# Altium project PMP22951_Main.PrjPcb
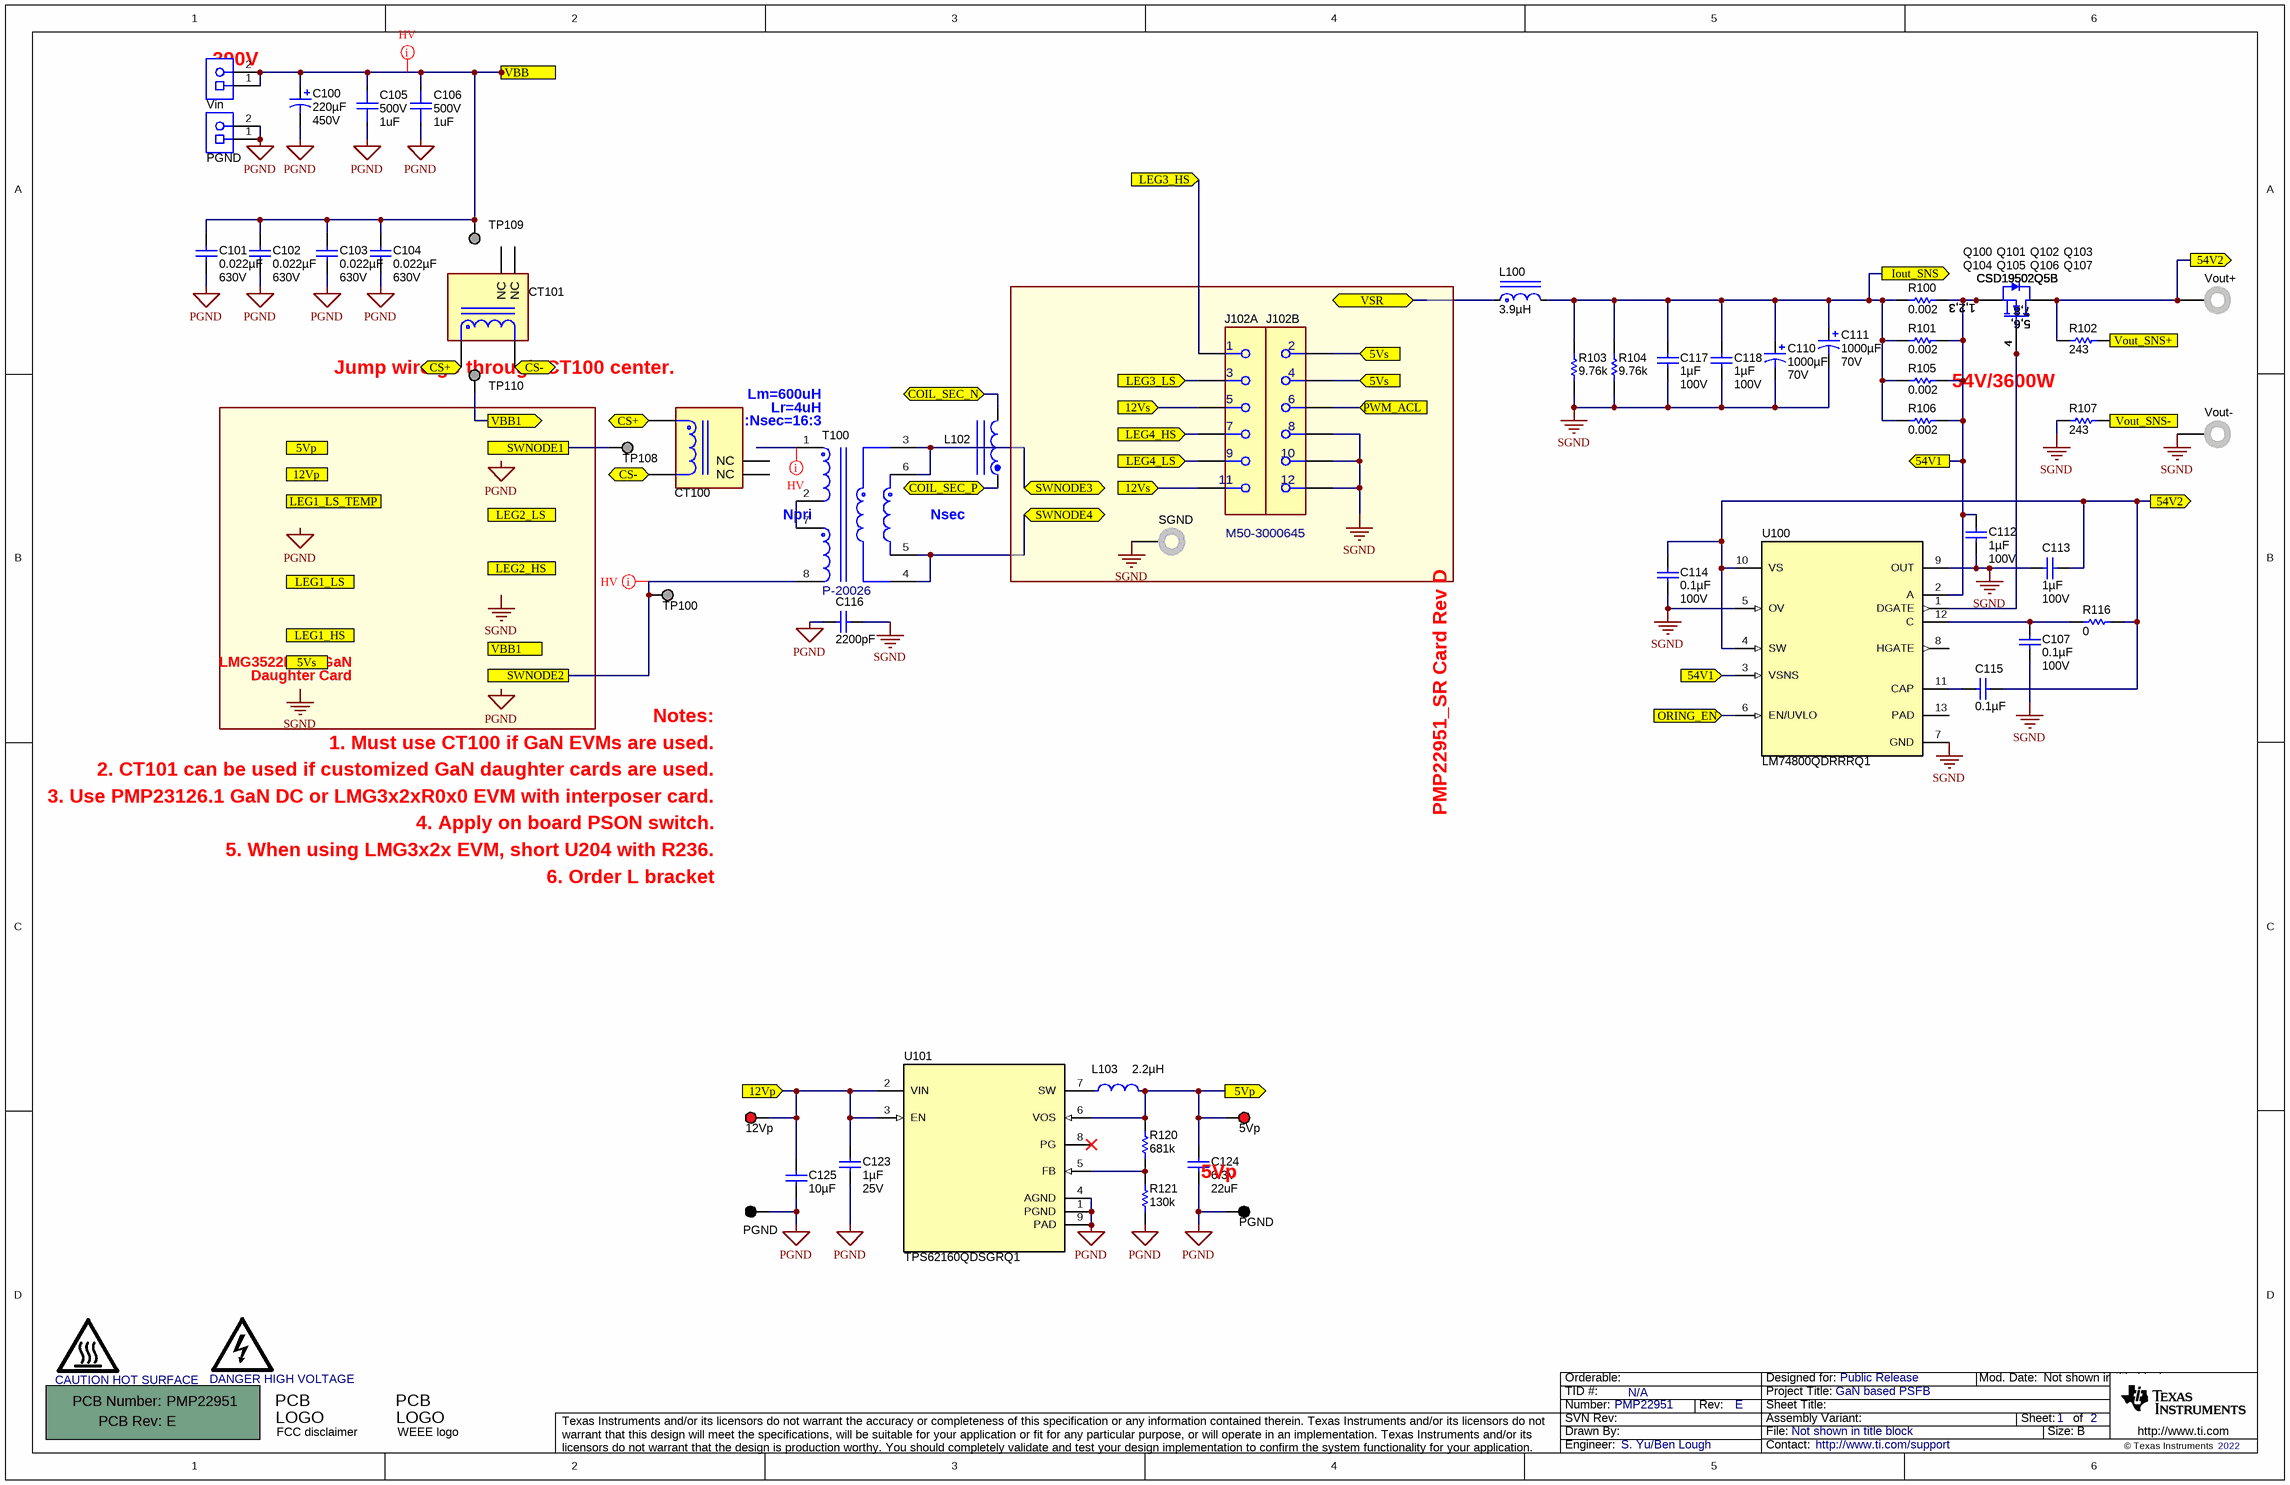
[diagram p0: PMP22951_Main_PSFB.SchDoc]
CopyrightYear: 2022; PCB_Layout: S. Yu/Ben Lough; PCB_Rev: E; PRJ_Customer: Public Release; PRJ_Engineer: S. Yu/Ben Lough; PRJ_Number: PMP22951; PRJ_Title: GaN based PSFB; SCH_Rev: E; TechSupport: http://www.ti.com/support; TID: N/A
2 sheets, 142 parts. Net scope: flat (ports and power ports of the same name join across sheets).
Board file: PMP22951_Main_PCB.PcbDoc
Sheets:
  PMP22951_Main_PSFB.SchDoc
  PMP22951_Main_Controller.SchDoc

## Sheet PMP22951_Main_PSFB.SchDoc
size 431 x 279 mm; Date: Not shown in title block; ApprovedBy: Not shown in title block; CheckedBy: Not shown in title block; Author: Not shown in title block; CompanyName: Not shown in title block; Engineer: Not shown in title block; Organization: Not shown in title block; Address1: Not shown in title block; Address2: Not shown in title block; Address3: Not shown in title block; Address4: Not shown in title block; DocumentNumber: 1; Revision: Use project parameter SCH_Rev; SheetNumber: 1; SheetTotal: 2; PageSetup: Record=PageOptions¦CenterHorizontal=True¦CenterVertical=True¦PrintScale=1.00¦XCorrection=1.00¦YCorrection=1.00¦PrintKind=0¦BorderSize=5000000¦LeftOffset=0¦BottomOffset=0¦Orientation=2¦PaperLength=1000¦PaperWidth=1000¦Scale=100¦PaperSource=15¦PrintQuality=600¦MediaType=1¦DitherType=10¦PaperKind=Letter¦PrintScaleMode=1

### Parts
(Parts that share a designator on the sheet are numbered #1, #2 ... from top to bottom, then left to right.)
5Vp  5000  [Keystone5000]  (value not drawn)
12Vp  5000  [Keystone5000]  (value not drawn)
!PCB100  Printed Circuit Board  (value not drawn)  (mechanical)
C100  ValueDisplayed: 220µF  Value2: 450V  [HXG_2500x4000]  (hidden comment: 450HXG220MEFCSN25X40)
C101  ValueDisplayed: 0.022µF  Value2: 630V  [1206]  (hidden comment: CL31B223KHHNNNE)
C102  ValueDisplayed: 0.022µF  Value2: 630V  [1206]  (hidden comment: CL31B223KHHNNNE)
C103  ValueDisplayed: 0.022µF  Value2: 630V  [1206]  (hidden comment: CL31B223KHHNNNE)
C104  ValueDisplayed: 0.022µF  Value2: 630V  [1206]  (hidden comment: CL31B223KHHNNNE)
C105  VDC_V: 500V  ValueDisplayed: 1uF  [FP-B58031U5105M062_SMD2-MFG]  (hidden comment: B58031U5105M062)
C106  VDC_V: 500V  ValueDisplayed: 1uF  [FP-B58031U5105M062_SMD2-MFG]  (hidden comment: B58031U5105M062)
C107  ValueDisplayed: 0.1µF  Value2: 100V  [0805_HV]  (hidden comment: C0805C104K1RACTU)
C110  ValueDisplayed: 1000µF  Value2: 70V  [HE_1800x2500]  (hidden comment: 70RXA1000M18X25)
C111  ValueDisplayed: 1000µF  Value2: 70V  [HE_1800x2500]  (hidden comment: 70RXA1000M18X25)
C112  ValueDisplayed: 1µF  Value2: 100V  [1206_180]  (hidden comment: GCM31CR72A105KA03)
C113  ValueDisplayed: 1µF  Value2: 100V  [1206_180]  (hidden comment: GCM31CR72A105KA03)
C114  ValueDisplayed: 0.1µF  Value2: 100V  [0805_HV]  (hidden comment: C0805C104K1RACTU)
C115  ValueDisplayed: 0.1µF  [0603]  (hidden comment: 06033C104JAT2A)
C116  ValueDisplayed: 2200pF  [E_900x700x900]  (hidden comment: DE6E3KJ222MN3A)
C117  ValueDisplayed: 1µF  Value2: 100V  [1206_180]  (hidden comment: GCM31CR72A105KA03)
C118  ValueDisplayed: 1µF  Value2: 100V  [1206_180]  (hidden comment: GCM31CR72A105KA03)
C123  Cap_F: 1µF  VDC_V: 25V  [0805_HV]  (hidden comment: C0805C105K3RACTU)
C124  VDC_V: 6.3V  ValueDisplayed: 22uF  [0805_HV]  (hidden comment: CL21A226KQQNNNE)
C125  ValueDisplayed: 10µF  [1206_180]  (hidden comment: GCM31CR71C106KA64L)
CT100  PAS6282NL  [FP-PAS6282NL_PTH_12MM5_4MM5-MFG]  (value not drawn)
CT101  PAS6282NL  [FP-PAS6282NL_PTH_12MM5_4MM5-MFG]  (value not drawn)
J102  M50-3000645  [FP-M50-3000645_HDR12-MFG]  (parts A,B of 2)
L100  value 3.9µH  [FP-PAL6567.421NL_PTH_IND_34MM0_9MM5-MFG]  (hidden comment: PAL6431.392NL)
L102  RLTI-1310  [RLTI-1310]  (value not drawn)
L103  Ind_H: 2.2µH  [FP-74438336010_SMD2-MFG]  (hidden comment: 74438336022)
LOGO100  CAUTION HOT SURFACE  [IEC_HotSurface_Small]  (no BOM)
LOGO101  DANGER HIGH VOLTAGE  [IEC_HighVoltage_Small]  (no BOM)
Logo102  FCC disclaimer  [FCC_disclaimer]  (no BOM)
Logo103  WEEE logo  [WEEE_Minimum]  (no BOM)
PGND#1  1715721  [PhoenixContact_1715721]  (value not drawn)
PGND#2  5001  [Keystone5001]  (value not drawn)
PGND#3  5001  [Keystone5001]  (value not drawn)
Q100  CSD19502Q5B  [DNK0008A]
Q101  CSD19502Q5B  [DNK0008A]
Q102  CSD19502Q5B  [DNK0008A]
Q103  CSD19502Q5B  [DNK0008A]
Q104  CSD19502Q5B  [DNK0008A]
Q105  CSD19502Q5B  [DNK0008A]
Q106  CSD19502Q5B  [DNK0008A]
Q107  CSD19502Q5B  [DNK0008A]
R100  ValueDisplayed: 0.002  [2010]  (hidden comment: PMR50HZPFV2L00)
R101  ValueDisplayed: 0.002  [2010]  (hidden comment: PMR50HZPFV2L00)
R102  ValueDisplayed: 243  [0603]  (hidden comment: CRCW0603243RFKEA)
R103  ValueDisplayed: 9.76k  [1206]  (hidden comment: RC1206FR-079K76L)
R104  ValueDisplayed: 9.76k  [1206]  (hidden comment: RC1206FR-079K76L)
R105  ValueDisplayed: 0.002  [2010]  (hidden comment: PMR50HZPFV2L00)
R106  ValueDisplayed: 0.002  [2010]  (hidden comment: PMR50HZPFV2L00)
R107  ValueDisplayed: 243  [0603]  (hidden comment: CRCW0603243RFKEA)
R116  ValueDisplayed: 0  [0603]  (hidden comment: CRCW06030000Z0EA)
R120  ValueDisplayed: 681k  [0402]  (hidden comment: CRCW0402681KFKED)
R121  ValueDisplayed: 130k  [0402]  (hidden comment: CRCW0402130KFKED)
SGND#1  575-4  [Keystone_575-4]  (value not drawn)
T100  P-20026  [FP-P-20026_SMT8_38MM0_24MM40-MFG]
TP100  Suggest using a net name here  [Mill-Max_0312-0-15-15-34-27-10-0]  (value not drawn)
TP108  Suggest using a net name here  [Mill-Max_0312-0-15-15-34-27-10-0]  (value not drawn)
TP109  Suggest using a net name here  [Mill-Max_0312-0-15-15-34-27-10-0]  (value not drawn)
TP110  Suggest using a net name here  [Mill-Max_0312-0-15-15-34-27-10-0]  (value not drawn)
U100  LM74800QDRRRQ1  [DRR0012E]
U101  TPS62160QDSGRQ1  [DSG0008A]
Vin  1715721  [PhoenixContact_1715721]  (value not drawn)
Vout+  575-4  [Keystone_575-4]  (value not drawn)
Vout-  575-4  [Keystone_575-4]  (value not drawn)

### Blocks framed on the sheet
PMP22951_SR Card Rev D: J102 SGND#1

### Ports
5Vp (in), 5Vp (out), 5Vs (in), 12Vp (in), 12Vs (in), 54V1 (in), 54V1 (out), 54V2 (out), COIL_SEC_N (bidir), COIL_SEC_P (bidir), CS+ (bidir), CS- (bidir), Iout_SNS (out), LEG1_HS (in), LEG1_LS (in), LEG1_LS_TEMP (in), LEG2_HS (in), LEG2_LS (in), LEG3_HS (in), LEG3_LS (in), LEG4_HS (in), LEG4_LS (in), ORING_EN (in), PWM_ACL (in), SWNODE1, SWNODE2, SWNODE3 (bidir), SWNODE4 (bidir), VBB1 (in), VBB1 (out), VBB (out), Vout_SNS+ (out), Vout_SNS- (out), VSR (bidir)

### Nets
PGND: C100.2(-) C101.2 C102.2 C103.2 C104.2 C105.1 C106.1 C116.1 C123.2 C124.2 C125.2 PGND#1.1 PGND#1.2 PGND#2.1 PGND#3.1 R121.1 U101.1(PGND) U101.4(AGND) U101.9(PAD)
SGND: C107.2 C110.2(-) C111.2(-) C112.1 C113.2 C114.2 C116.2 C117.2 C118.2 J102.8 J102.10 J102.12 R103.1 R104.1 R107.1 SGND#1.1 U100.5(OV) U100.7(GND) U100.9(OUT) Vout-.1
5Vp: 5Vp.1 C124.1 L103.2 R120.2 U101.6(VOS) ; port 5Vp
5Vs: J102.2 J102.4 ; port 5Vs
12Vp: 12Vp.1 C123.1 C125.1 U101.2(VIN) U101.3(EN) ; port 12Vp
12Vs: J102.5 J102.11 ; port 12Vs
54V1: C112.2 Q100.1(S) Q100.2(S) Q100.3(S) Q101.1(S) Q101.2(S) Q101.3(S) Q102.1(S) Q102.2(S) Q102.3(S) Q103.1(S) Q103.2(S) Q103.3(S) Q104.1(S) Q104.2(S) Q104.3(S) Q105.1(S) Q105.2(S) Q105.3(S) Q106.1(S) Q106.2(S) Q106.3(S) Q107.1(S) Q107.2(S) Q107.3(S) R100.2 R101.2 R105.2 R106.2 U100.2(A) U100.3(VSNS) ; port 54V1
54V2: C113.1 C114.1 C115.1 Q100.5(D) Q100.6(D) Q100.7(D) Q100.8(D) Q100.9(D) Q101.5(D) Q101.6(D) Q101.7(D) Q101.8(D) Q101.9(D) Q102.5(D) Q102.6(D) Q102.7(D) Q102.8(D) Q102.9(D) Q103.5(D) Q103.6(D) Q103.7(D) Q103.8(D) Q103.9(D) Q104.5(D) Q104.6(D) Q104.7(D) Q104.8(D) Q104.9(D) Q105.5(D) Q105.6(D) Q105.7(D) Q105.8(D) Q105.9(D) Q106.5(D) Q106.6(D) Q106.7(D) Q106.8(D) Q106.9(D) Q107.5(D) Q107.6(D) Q107.7(D) Q107.8(D) Q107.9(D) R102.1 R116.2 U100.4(SW) U100.10(VS) Vout+.1 ; port 54V2
COIL_SEC_N: L102.2 ; port COIL_SEC_N
COIL_SEC_P: L102.1 ; port COIL_SEC_P
CS+: CT100.1 CT101.1 ; port CS+
CS-: CT100.3 CT101.3 ; port CS-
Iout_SNS: C110.1(+) C111.1(+) C117.1 C118.1 L100.2(F) R100.1 R101.1 R103.2 R104.2 R105.1 R106.1 ; port Iout_SNS
LEG3_HS: J102.1 ; port LEG3_HS
LEG3_LS: J102.3 ; port LEG3_LS
LEG4_HS: J102.7 ; port LEG4_HS
LEG4_LS: J102.9 ; port LEG4_LS
ORING_EN: U100.6(EN/UVLO) ; port ORING_EN
PWM_ACL: J102.6 ; port PWM_ACL
SWNODE1: TP108.1 ; port SWNODE1
SWNODE2: T100.8 TP100.1 ; port SWNODE2
SWNODE3: T100.3 T100.6 ; port SWNODE3
SWNODE4: T100.4 T100.5 ; port SWNODE4
VBB: C100.1(+) C101.1 C102.1 C103.1 C104.1 C105.2 C106.2 TP109.1 Vin.1 Vin.2 ; port VBB
VBB1: TP110.1 ; port VBB1
Vout_SNS+: R102.2 ; port Vout_SNS+
Vout_SNS-: R107.2 ; port Vout_SNS-
VSR: L100.1(S) ; port VSR
NetC107_1: C107.1 R116.1 U100.12(C)
NetC115_2: C115.2 U100.11(CAP)
NetL103_1: L103.1 U101.7(SW)
NetQ100_4: Q100.4(G) Q101.4(G) Q102.4(G) Q103.4(G) Q104.4(G) Q105.4(G) Q106.4(G) Q107.4(G) U100.1(DGATE)
NetR120_1: R120.1 R121.2 U101.5(FB)
NetT100_2: T100.2 T100.7

Not connected (* = marked no-connect by the designer): CT100 2(NC) 4(NC); CT101 2(NC) 4(NC); T100 1; U100 8(HGATE) 13(PAD); U101 8(PG)*

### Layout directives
net class HV: NetT100_1, SWNODE2, VBB

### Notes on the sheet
- 390V
- Jump wire go through CT100 center.
- (near T100) Npri:Nsec=16:3
- (near T100) Lm=600uH
- (near T100) Lr=4uH
- 54V/3600W
- Npri
- (near T100) Nsec
- Daughter Card
- LMG3522R030 GaN
- Notes:
- 1. Must use CT100 if GaN EVMs are used.
- 2. CT101 can be used if customized GaN daughter cards are used.
- 3. Use PMP23126.1 GaN DC or LMG3x2xR0x0 EVM with interposer card.
- 4. Apply on board PSON switch.
- 6. Order L bracket
- 5. When using LMG3x2x EVM, short U204 with R236.
- 5Vp
- Labels drawn without touching a wire or pin: PGND, SGND

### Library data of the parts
5Vp 12Vp = 5000: Test Point, Miniature, Red, TH; Manufacturer: Keystone; CompType: Test Point Loop; ContactFinish: Silver; Green_Lifecycle: Active; Green_REACh: Passed
!PCB100 = CMP-0003618-2: Manufacturer: Any; PartNumber: PMP22951
C100 = 450HXG220MEFCSN25X40: CAP, AL, 220 µF, 450 V, +/- 20%, TH; Manufacturer: Rubycon; Polarized: Y; CompType: Capacitor; Value: 220uF; U/M: EA; Cap_F: 0.00022; Tolerance_%: 20; VDC_V: 450; IRMS_A: 1.97; TaMin_C: -25; TaMax_C: 105; Cap_Case: 25x40mm; SizeAreaWB_mm2: 729; SizeArea_mm2: 625; SizeX_mm: 25; SizeZ_mm: 42; AEC Category: Q200; AEC Qualified: N
C101-C104 = VJ1206Y223KXGAT5Z: CAP, CERM, 0.022 µF, 630 V,+/- 10%, X7R, 1206; Manufacturer: Samsung Electro-Mechanics; Polarized: N; CompType: Capacitor; Value: 0.022uF; U/M: EA; Cap_F: 0.000000022; Tolerance_%: 10; VDC_V: 630; TaMin_C: -55; TaMax_C: 125; SizeArea_mm2: 5.12; SizeAreaWB_mm2: 10.92; SizeX_mm: 3.2; SizeY_mm: 1.6; SizeZ_mm: 1.35; AEC Category: Q200
C105 C106 = CMP-0091050-1: TDK 1µF Multilayer Ceramic Capacitor MLCC 500V dc ±20% SMD; AEC Grade: Grade 0; AEC Qualified: Yes; SizeZ_mm: 4.5mm
C107 C114 = C0805C104K1RACTU: CAP, CERM, 0.1 µF, 100 V,+/- 10%, X7R, 0805; Manufacturer: Kemet; Polarized: N; CompType: Capacitor; Value: 0.1uF; U/M: EA; Cap_F: 0.0000001; Tolerance_%: 10; ESR_ohm: 0.064; Value1: 0.064 ohm; VDC_V: 100; IRMS_A: 1.64; TaMin_C: -55; TaMax_C: 125; Cap_Case: 0805; SizeArea_mm2: 2.5; SizeAreaWB_mm2: 6.75; SizeX_mm: 2; SizeY_mm: 1.25; SizeZ_mm: 1.45; AEC Category: Q200; Green_Lifecycle: Active; Green_REACh: Passed
C110 C111 = UHE1H122MHD6: CAP, AL, 1000 µF, 70 V, +/- 20%, TH; Manufacturer: Rubycon; Polarized: Y; CompType: Capacitor; Value: 1000uF; U/M: EA; Cap_F: 0.0012; Tolerance_%: 20; IRMS_A: 2.74; TaMin_C: -40; TaMax_C: 105; Cap_Case: 18x25mm; SizeAreaWB_mm2: 400; SizeArea_mm2: 324; SizeX_mm: 18; SizeZ_mm: 27; AEC Category: Q200; AEC Qualified: N
C112 C113 C117 C118 = GCM31CR72A105KA03: CAP, CERM, 1 µF, 100 V,+/- 10%, X7R, AEC-Q200 Grade 1, 1206; Manufacturer: MuRata; Polarized: N; CompType: Capacitor; Value: 1uF; U/M: EA; Cap_F: 0.000001; Tolerance_%: 10; VDC_V: 100; TaMin_C: -55; TaMax_C: 125; Cap_Case: 1206; SizeArea_mm2: 5.12; SizeAreaWB_mm2: 10.92; SizeX_mm: 3.2; SizeY_mm: 1.6; SizeZ_mm: 1.8; AEC Category: Q200; AEC Qualified: Y; AEC Grade: 1
C115 = 06033C104JAT2A: CAP, CERM, 0.1 µF, 25 V,+/- 5%, X7R, 0603; Manufacturer: AVX; Polarized: N; CompType: Capacitor; Value: 0.1uF; U/M: EA; Cap_F: 0.0000001; Tolerance_%: 5; ESR_ohm: 0.05; Value1: 0.05 ohm; VDC_V: 25; Value2: 25V; TaMin_C: -55; TaMax_C: 125; SizeArea_mm2: 1.28; SizeAreaWB_mm2: 4.68; SizeX_mm: 1.6; SizeY_mm: 0.8; SizeZ_mm: 1; AEC Category: Q200; Green_Lifecycle: Active; Green_REACh: Passed
C116 = DE6E3KJ222MN3A: CAP, CERM, 2200 pF, 300 V, +/- 20%, E, TH, 2- Leads, Body 9x7mm, Pin Spacing 7.5mm; Manufacturer: MuRata; Polarized: N; CompType: Capacitor; Value: 2200pF; U/M: EA; Cap_F: 0.0000000022; Tolerance_%: 20; Value1: Unknown; VDC_V: 300; Value2: 300V; TaMin_C: -40; TaMax_C: 125; Cap_Case: 9x7x9mm; SizeArea_mm2: 63; SizeAreaWB_mm2: 99; SizeX_mm: 9; SizeY_mm: 7; SizeZ_mm: 12; AEC Category: Q200
C123 = CMP-0007728-2: CAP, CERM, 1 uF, 25 V, +/- 10%, X7R, 0805; Manufacturer: Kemet; TaMin_C: -55°C; Polarized: N; SizeAreaWB_mm2: 6.75; Value1: Unknown; U/M: EA; Value: 1uF; TaMax_C: 125°C; SizeZ_mm: 1.45; SizeX_mm: 2; SizeY_mm: 1.25; Cap_Case: 0805; SizeArea_mm2: 2.5; CompType: Capacitor; AEC Category: Q200
C124 = CMP-0007989-2: CAP, CERM, 22 uF, 6.3 V, +/- 10%, X5R, 0805; Manufacturer: Samsung Electro-Mechanics; TaMin_C: -55°C; Polarized: N; SizeAreaWB_mm2: 6.75; Value1: Unknown; U/M: EA; Value: 22uF; TaMax_C: 85°C; SizeZ_mm: 1.45; SizeX_mm: 2; SizeY_mm: 1.25; Cap_Case: 0805; SizeArea_mm2: 2.5; CompType: Capacitor; Cap_F: 22µF; AEC Category: Q200
C125 = GCM31CR71C106KA64L: CAP, CERM, 10 µF, 16 V,+/- 10%, X7R, AEC-Q200 Grade 1, 1206; Manufacturer: MuRata; Polarized: N; CompType: Capacitor; Value: 10uF; U/M: EA; Cap_F: 0.00001; Tolerance_%: 10; VDC_V: 16; Value2: 16V; TaMin_C: -55; TaMax_C: 125; Cap_Case: 1206; SizeArea_mm2: 5.12; SizeAreaWB_mm2: 10.92; SizeX_mm: 3.2; SizeY_mm: 1.6; SizeZ_mm: 1.8; AEC Category: Q200; AEC Qualified: Y; AEC Grade: 1; Green_Lifecycle: Active; Green_REACh: Passed
CT100 CT101 = CMP-0091119-1: Inductor PTH 3.3mH 300mOhm; Manufacturer: Pulse Electronics; SizeZ_mm: 13.5mm; AEC Qualified: No; DCR_ohm: 3d; Test Frequency: 100kHz
J102 = CMP-0094055-1: 12 Position Receptacle Connector 0.050" (1.27mm) Through Hole Gold; Manufacturer: Harwin; AEC Qualified: No; Is Female: yes; ContactFinish: Gold,Nickel; SizeZ_mm: 4.55mm; Current_A: 1A; Conn Gender: Female; Conn Orientation: Vertical; Row_Count: 2
L100 = CMP-0093530-1: INDUCTOR, POWER, EP33, TH 0.42uH 20% 10kHz 0.06mOhm DCR MAX 300A Isat; Manufacturer: Pulse; AEC Qualified: No; SizeZ_mm: 25mm
L102 = CMP-0086080-1: Inductor, Toroid, 7 µH, 1.155 ohm, TH; Manufacturer: Renco Electronics; SizeZ_mm: 18.669; SizeAreaWB_mm2: 135.836668; SizeX_mm: 4.572; AEC Qualified: N; AEC Category: Q200; Ind_H: 7µH; DCR_ohm: 1.155; Value: 7uH; Value2: A; SizeArea_mm2: 85.354668
L103 = CMP-0087867-1: 2.2µH Shielded Molded Inductor 2.4A 67mOhm Max 2-SMD; Manufacturer: Wurth Electronics; SizeZ_mm: 2mm; Material: Metal Composite; Isat: 4.3A; Symbol Name: SYM-74438336010; DCR_ohm: 0.032; AEC Grade: Grade 1; AEC Qualified: Yes
LOGO100 = CMP-0074837-1: IEC 61010-1 Hot Surface Warning; Library Reference: IEC_HotSurface; SymbolCreator: a0412235
LOGO101 = CMP-0074835-1: IEC 61010-1 High Voltage Warning; Library Reference: IEC_HighVoltage; SymbolCreator: a0412235
Logo102 = CMP-0074847-1: FCC_disclaimer; Library Reference: Logo
Logo103 = CMP-0074769-1
PGND#1 Vin = CMP-0055471-1: Terminal Block, 5.08 mm, 2x1, TH; Manufacturer: Phoenix Contact; Cert_VDE: Y; CNHeader: FALSE; Current_A: 17.5A; Green_Lifecycle: Not Set; Gender: Female; Cert_CULUS: N; Green_REACh: Incomplete; Voltage_V: 400V; Row_Count: 1; Pitch_mm: 5.08; ContactFinish: Tin; CT: TRUE
PGND#2 PGND#3 = 5001: Test Point, Miniature, Black, TH; Manufacturer: Keystone; CompType: Test Point Loop; ContactFinish: Silver; Green_Lifecycle: Active; Green_REACh: Passed
Q100-Q107 = CMP-0000915-2: MOSFET, N-CH, 80 V, 100 A, DNK0008A (VSON-CLIP-8); Alternate Manufacturer: None; Manufacturer: Texas Instruments; SizeZ_mm: 1; ChType: N; Value2: 48 nC; VdsMax_V: 80V; SizeX_mm: 6; SizeY_mm: 5; Vgs_V: 20V; Value: 80V; SizeArea_mm2: 30; AEC Category: Q101; IdsMax_A: 100A; SizeAreaWB_mm2: 56; U/M: EA; QgTyp_nC: 48
R100 R101 R105 R106 = PMR50HZPFV2L00: RES, 0.002, 1%, 1 W, 2010; Manufacturer: Rohm; CompType: Resistor; Value: 0.002; Value_Code: 2L000; Tolerance_%: 1; Value2: 1W; TempCo: 100 ppm/C; SizeArea_mm2: 12.5; SizeX_mm: 5; SizeY_mm: 2.5; SizeZ_mm: 1.66; U/M: EA; AEC Category: Q200
R102 R107 = CRCW0603243RFKEA: RES, 243, 1%, 0.1 W, 0603; Manufacturer: Vishay-Dale; CompType: Resistor; Value: 243; Value_Code: 243R; Tolerance_%: 1; Power_W: 0.1; Value2: 0.1W; VDC_V: 75; TempCo: 100 ppm/C; SizeArea_mm2: 1.28; SizeX_mm: 1.6; SizeY_mm: 0.8; EIA_Code: E96; U/M: EA; AEC Category: Q200
R103 R104 = RC1206FR-079K76L: RES, 9.76 k, 1%, 0.25 W, 1206; Manufacturer: Yageo America; CompType: Resistor; Value: 9.76k; Res_ohm: 9760; Value_Code: 9k76; Tolerance_%: 1; Power_W: 0.25; Value2: 0.25W; VDC_V: 200; TempCo: 100 ppm/C; SizeArea_mm2: 5.12; SizeX_mm: 3.2; SizeY_mm: 1.6; SizeZ_mm: 1.35; EIA_Code: E96; U/M: EA; AEC Category: Q200
R116 = CRCW06030000Z0EA: RES, 0, 5%, 0.1 W, 0603; Manufacturer: Vishay-Dale; CompType: Resistor; Value: 0; Value_Code: 0000; Tolerance_%: 5; Power_W: 0.1; Value2: 0.1W; VDC_V: 75; TempCo: 200 ppm/C; SizeArea_mm2: 1.28; SizeX_mm: 1.6; SizeY_mm: 0.8; SizeZ_mm: 1; EIA_Code: E24; U/M: EA; AEC Category: Q200; Green_Lifecycle: Active; Green_REACh: Passed
R120 = CMP-0026504-2: RES, 681 k, 1%, 0.063 W, AEC-Q200 Grade 0, 0402; Manufacturer: Vishay-Dale; Power_W: 63mW; TempCo: 100 ppm/C; Value: 681k; EIA_Code: E96; SizeX_mm: 1; SizeY_mm: 0.5; SizeZ_mm: 0.6; Value2: 0.063W; CompType: Resistor; AEC Qualified: Y; VDC_V: 50V; AEC Category: Q200; AEC Grade: 0
R121 = CMP-0025997-3: RES, 130 k, 1%, 0.063 W, AEC-Q200 Grade 0, 0402; Manufacturer: Vishay-Dale; Power_W: 63mW; TempCo: 100 ppm/C; Value: 130k; EIA_Code: E96; SizeX_mm: 1; SizeY_mm: 0.5; SizeZ_mm: 0.6; Value2: 0.063W; CompType: Resistor; AEC Qualified: Y; VDC_V: 50V; AEC Category: Q200; AEC Grade: 0
SGND#1 Vout+ Vout- = 575-4: Standard Banana Jack, Uninsulated, 5.5mm; Manufacturer: Keystone; CompType: Connector; U/M: EA
T100 = CMP-0091539-2: TRANSFORMER; Manufacturer: Delta; AEC Qualified: No; DCR_ohm: 0.017; Rsec1_ohm: 6m; SizeZ_mm: 32.6mm; Ind_H: 450µH; Voltage_Isolation_Vrms: 3kV; Standoff Height: 2.4mm
TP100 TP108-TP110 = 0312-0-15-15-34-27-10-0: Pin Receptacle, .032-.046" .075" Dia, Gold, TH; Manufacturer: Mill-Max; Gender: Female
U100 = CMP-0860988-1: Ideal Diode Controller with Load Dump Protection, DRR0012E (WSON-12); Alternate Manufacturer: Texas Instruments; CompType: IC; AEC Qualified: Y; SizeY_mm: 3; SizeZ_mm: 0.8; AEC Category: Q200; SizeArea_mm2: 9; SizeAreaWB_mm2: 16
U101 = CMP-0067100-2: 3V-17V 1A Automotive Step-Down Converters in 2x2SON, DSG0008A (WSON-8); Alternate PartNumber: TPS62160QDSGTQ1; Manufacturer: Texas Instruments; SizeZ_mm: 0.8; SizeX_mm: 2.0; SizeArea_mm2: 4.0; CompType: IC; U/M: EA; SizeAreaWB_mm2: 9.0

## Sheet PMP22951_Main_Controller.SchDoc
size 431 x 279 mm; Date: Not shown in title block; ApprovedBy: Not shown in title block; CheckedBy: Not shown in title block; Author: Not shown in title block; CompanyName: Not shown in title block; Engineer: Not shown in title block; Organization: Not shown in title block; Address1: Not shown in title block; Address2: Not shown in title block; Address3: Not shown in title block; Address4: Not shown in title block; DocumentNumber: 2; Revision: Use project parameter SCH_Rev; SheetNumber: 2; SheetTotal: 2; PageSetup: Record=PageOptions¦CenterHorizontal=True¦CenterVertical=True¦PrintScale=1.00¦XCorrection=1.00¦YCorrection=1.00¦PrintKind=0¦BorderSize=5000000¦LeftOffset=0¦BottomOffset=0¦Orientation=2¦PaperLength=1000¦PaperWidth=1000¦Scale=100¦PaperSource=15¦PrintQuality=600¦MediaType=1¦DitherType=10¦PaperKind=Letter¦PrintScaleMode=1
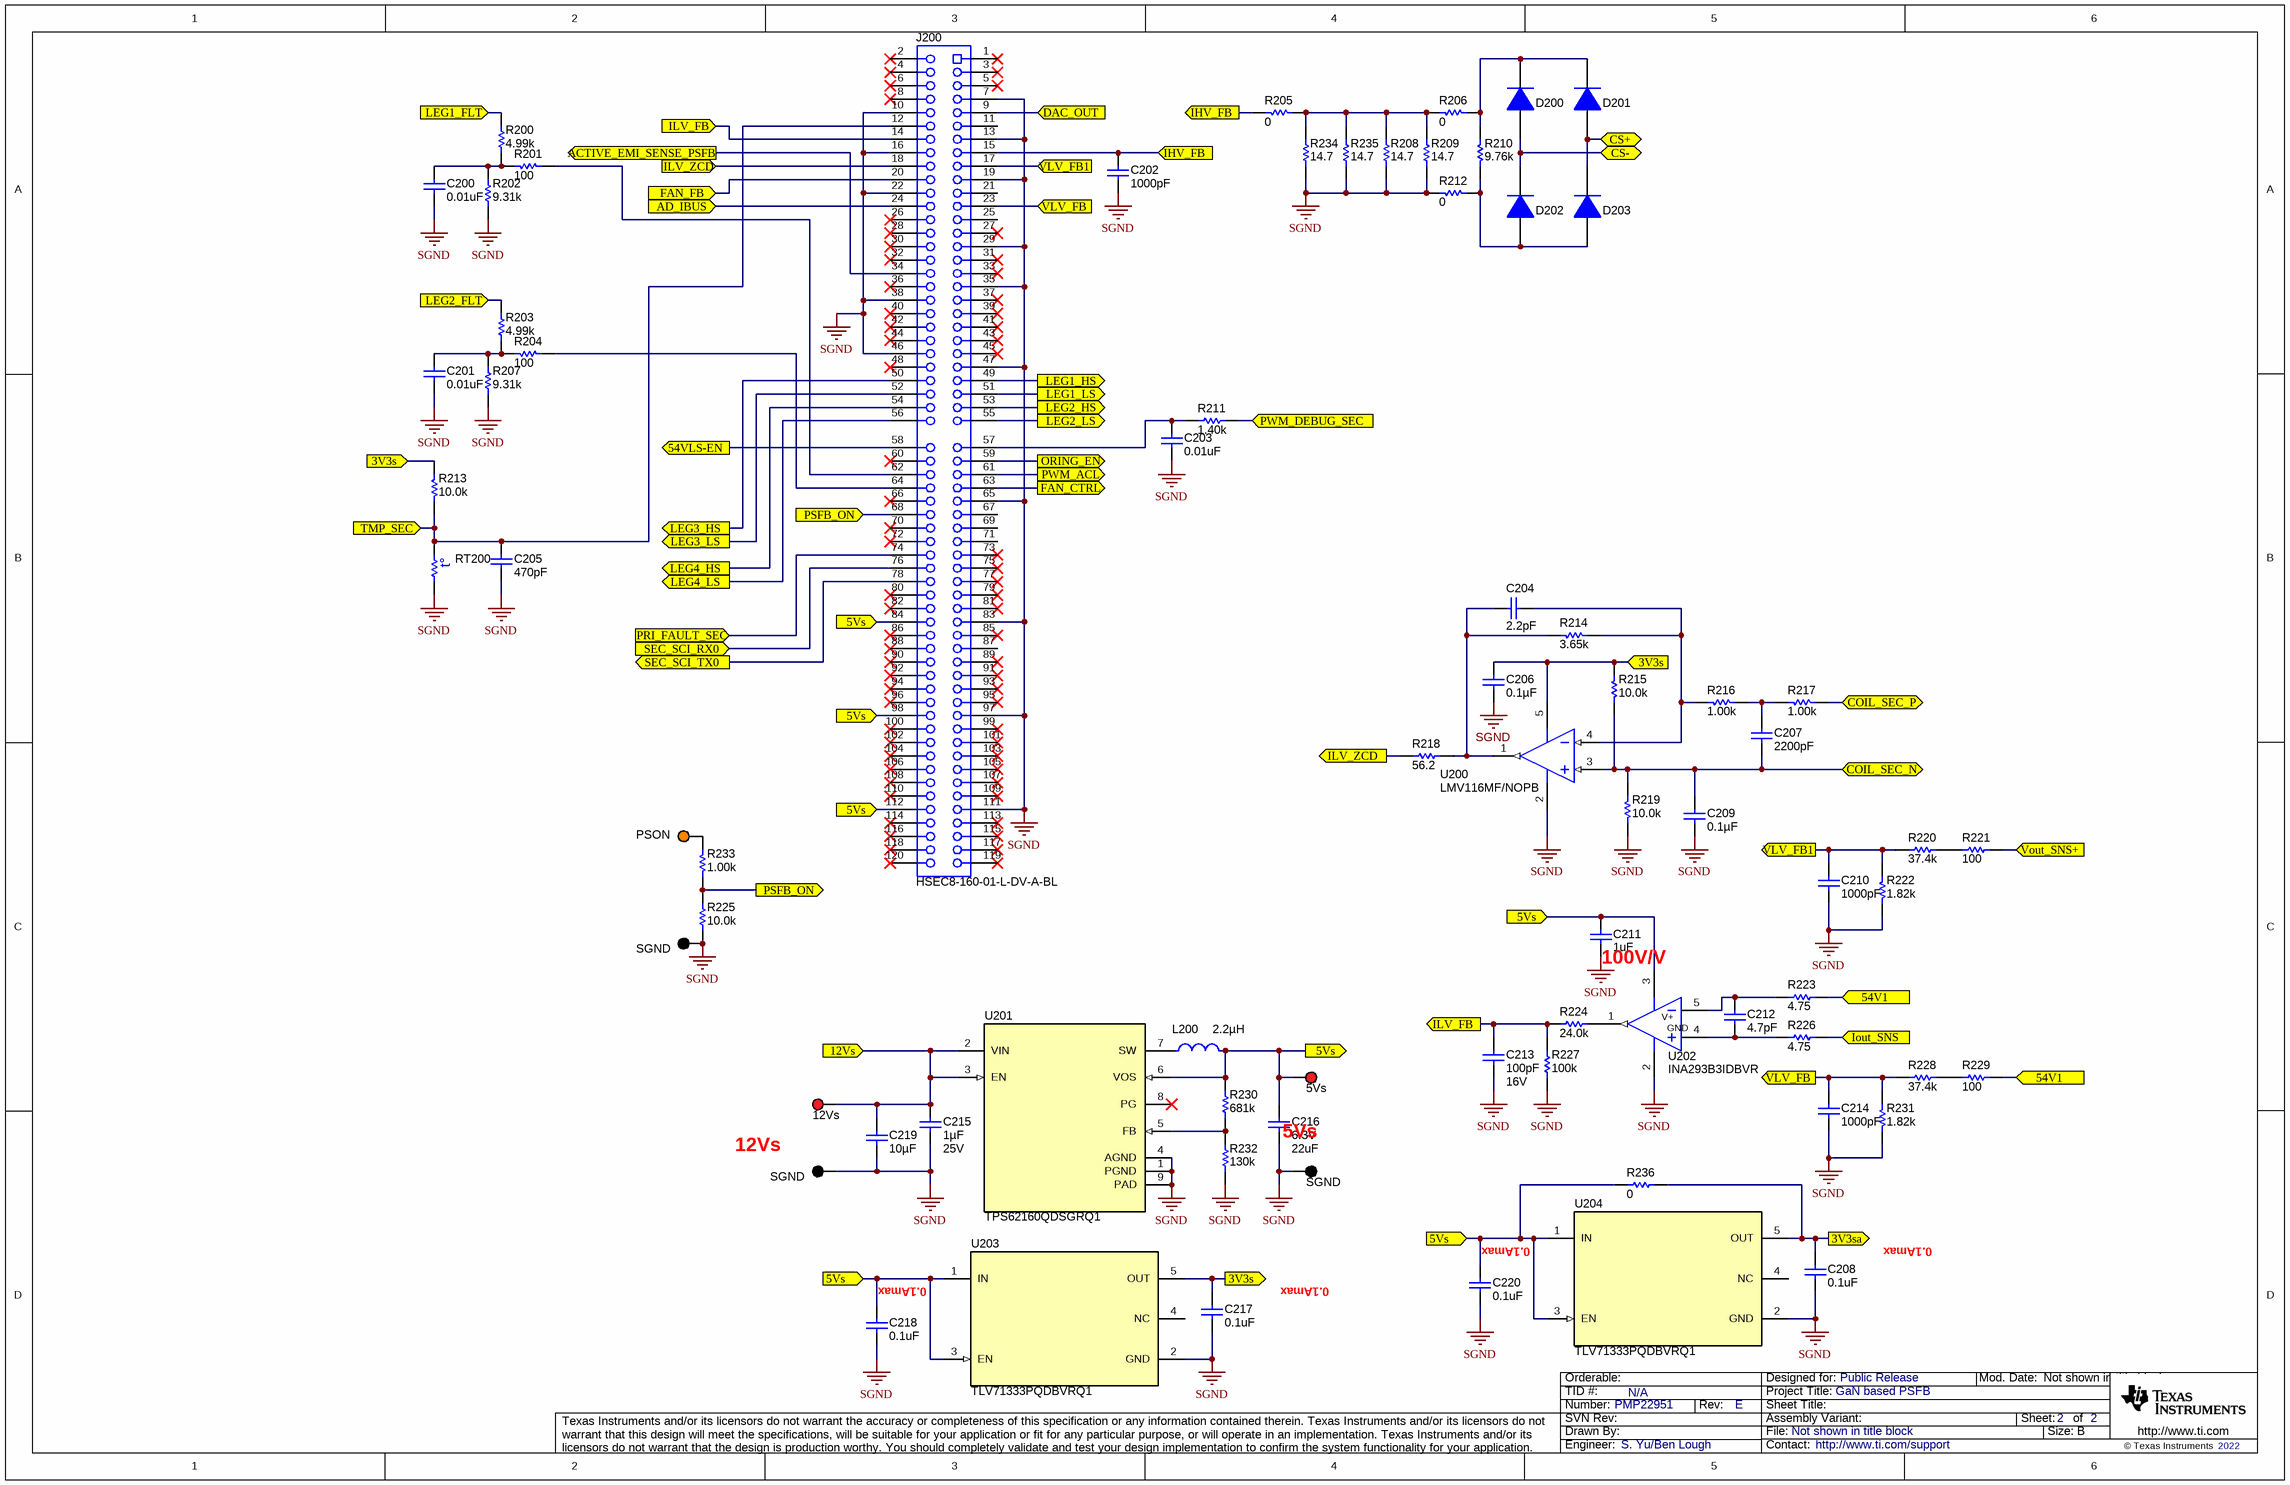
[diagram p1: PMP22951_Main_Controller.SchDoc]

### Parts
(Parts that share a designator on the sheet are numbered #1, #2 ... from top to bottom, then left to right.)
5Vs  5000  [Keystone5000]  (value not drawn)
12Vs  5000  [Keystone5000]  (value not drawn)
C200  ValueDisplayed: 0.01uF  [0402]  (hidden comment: GRM155R70J103KA01D)
C201  ValueDisplayed: 0.01uF  [0402]  (hidden comment: GRM155R70J103KA01D)
C202  ValueDisplayed: 1000pF  [0402]  (hidden comment: 885012205044)
C203  ValueDisplayed: 0.01uF  [0402]  (hidden comment: GRM155R70J103KA01D)
C204  ValueDisplayed: 2.2pF  [0402]  (hidden comment: GRM1555C1H2R2BA01D)
C205  ValueDisplayed: 470pF  [0402]  (hidden comment: CGA2B2X7R1H471K050BA)
C206  ValueDisplayed: 0.1µF  [0402]  (hidden comment: 0402YC104KAT2A)
C207  ValueDisplayed: 2200pF  [0402]  (hidden comment: CGA2B2X7R1H222K050BA)
C208  ValueDisplayed: 0.1uF  [0402]  (hidden comment: GRM155R70J104KA01D)
C209  ValueDisplayed: 0.1µF  [0402]  (hidden comment: 0402YC104KAT2A)
C210  ValueDisplayed: 1000pF  [0603]  (hidden comment: 06035A102KAT2A)
C211  ValueDisplayed: 1uF  [0603]  (hidden comment: C1608X7R1E105K080AB)
C212  ValueDisplayed: 4.7pF  [0402]  (hidden comment: GRM1555C1E4R7CA01D)
C213  ValueDisplayed: 100pF  Value2: 16V  [0402]  (hidden comment: 0402YC101KAT2A)
C214  ValueDisplayed: 1000pF  [0603]  (hidden comment: 06035A102KAT2A)
C215  Cap_F: 1µF  VDC_V: 25V  [0805_HV]  (hidden comment: C0805C105K3RACTU)
C216  VDC_V: 6.3V  ValueDisplayed: 22uF  [0805_HV]  (hidden comment: CL21A226KQQNNNE)
C217  ValueDisplayed: 0.1uF  [0402]  (hidden comment: GRM155R70J104KA01D)
C218  ValueDisplayed: 0.1uF  [0402]  (hidden comment: GRM155R70J104KA01D)
C219  ValueDisplayed: 10µF  [1206_180]  (hidden comment: GCM31CR71C106KA64L)
C220  ValueDisplayed: 0.1uF  [0402]  (hidden comment: GRM155R70J104KA01D)
D200  BAS316,115  [SOD-323]  (value not drawn)
D201  BAS316,115  [SOD-323]  (value not drawn)
D202  BAS316,115  [SOD-323]  (value not drawn)
D203  BAS316,115  [SOD-323]  (value not drawn)
J200  HSEC8-160-01-L-DV-A-BL  [controlCARD-120HSEC]
L200  Ind_H: 2.2µH  [FP-74438336010_SMD2-MFG]  (hidden comment: 74438336022)
PSON  5003  [Keystone5003]  (value not drawn)
R200  ValueDisplayed: 4.99k  [0402]  (hidden comment: CRCW04024K99FKED)
R201  ValueDisplayed: 100  [0603]  (hidden comment: CRCW0603100RFKEA)
R202  ValueDisplayed: 9.31k  [0402]  (hidden comment: CRCW04029K31FKED)
R203  ValueDisplayed: 4.99k  [0402]  (hidden comment: CRCW04024K99FKED)
R204  ValueDisplayed: 100  [0603]  (hidden comment: CRCW0603100RFKEA)
R205  ValueDisplayed: 0  [0402]  (hidden comment: CRCW04020000Z0ED)
R206  ValueDisplayed: 0  [0402]  (hidden comment: CRCW04020000Z0ED)
R207  ValueDisplayed: 9.31k  [0402]  (hidden comment: CRCW04029K31FKED)
R208  ValueDisplayed: 14.7  [1206]  (hidden comment: CRCW120614R7FKEA)
R209  ValueDisplayed: 14.7  [1206]  (hidden comment: CRCW120614R7FKEA)
R210  ValueDisplayed: 9.76k  [0603]  (hidden comment: RC0603FR-079K76L)
R211  value 1.40k  [0402]  (hidden comment: CRCW04021K40FKED)
R212  ValueDisplayed: 0  [0402]  (hidden comment: CRCW04020000Z0ED)
R213  ValueDisplayed: 10.0k  [0402]  (hidden comment: CRCW040210K0FKED)
R214  ValueDisplayed: 3.65k  [0402]  (hidden comment: CRCW04023K65FKED)
R215  ValueDisplayed: 10.0k  [0402]  (hidden comment: CRCW040210K0FKED)
R216  ValueDisplayed: 1.00k  [0402]  (hidden comment: CRCW04021K00FKED)
R217  ValueDisplayed: 1.00k  [0402]  (hidden comment: CRCW04021K00FKED)
R218  ValueDisplayed: 56.2  [0402]  (hidden comment: RC0402FR-0756R2L)
R219  ValueDisplayed: 10.0k  [0402]  (hidden comment: CRCW040210K0FKED)
R220  ValueDisplayed: 37.4k  [1206]  (hidden comment: CRCW120637K4FKEA)
R221  ValueDisplayed: 100  [0603]  (hidden comment: CRCW0603100RFKEA)
R222  ValueDisplayed: 1.82k  [0603]  (hidden comment: RC0603FR-071K82L)
R223  ValueDisplayed: 4.75  [0603]  (hidden comment: RC0603FR-074R75L)
R224  ValueDisplayed: 24.0k  [0603]  (hidden comment: RC0603FR-0724KL)
R225  ValueDisplayed: 10.0k  [1206]  (hidden comment: CRCW120610K0FKEA)
R226  ValueDisplayed: 4.75  [0603]  (hidden comment: RC0603FR-074R75L)
R227  ValueDisplayed: 100k  [0603]  (hidden comment: CRCW0603100KFKEA)
R228  ValueDisplayed: 37.4k  [1206]  (hidden comment: CRCW120637K4FKEA)
R229  ValueDisplayed: 100  [0603]  (hidden comment: CRCW0603100RFKEA)
R230  ValueDisplayed: 681k  [0402]  (hidden comment: CRCW0402681KFKED)
R231  ValueDisplayed: 1.82k  [0603]  (hidden comment: RC0603FR-071K82L)
R232  ValueDisplayed: 130k  [0402]  (hidden comment: CRCW0402130KFKED)
R233  ValueDisplayed: 1.00k  [0402]  (hidden comment: CRCW04021K00FKED)
R234  ValueDisplayed: 14.7  [1206]  (hidden comment: CRCW120614R7FKEA)
R235  ValueDisplayed: 14.7  [1206]  (hidden comment: CRCW120614R7FKEA)
R236  ValueDisplayed: 0  [1206]  (hidden comment: CRCW12060000Z0EA)
RT200  TMP6131DECR  [DEC0002A]  (value not drawn)
SGND#2  5001  [Keystone5001]  (value not drawn)
SGND#3  5001  [Keystone5001]  (value not drawn)
SGND#4  5001  [Keystone5001]  (value not drawn)
U200  LMV116MF/NOPB  [DBV0005A_N]
U201  TPS62160QDSGRQ1  [DSG0008A]
U202  INA293B3IDBVR  [DBV0005A_L]
U203  TLV71333PQDBVRQ1  [DBV0005A_N]
U204  TLV71333PQDBVRQ1  [DBV0005A_N]

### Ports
3V3s (in), 3V3s (out), 3V3sa (out), 5Vs (in), 5Vs (out), 12Vs (in), 54V1 (in), 54VLS-EN (out), ACTIVE_EMI_SENSE_PSFB (out), AD_IBUS (in), COIL_SEC_N (bidir), COIL_SEC_P (bidir), CS+ (bidir), CS- (bidir), DAC_OUT (in), FAN_CTRL (out), FAN_FB (in), IHV_FB (in), IHV_FB (out), ILV_FB (in), ILV_FB (out), ILV_ZCD (in), ILV_ZCD (out), Iout_SNS (in), LEG1_FLT (in), LEG1_HS (out), LEG1_LS (out), LEG2_FLT (in), LEG2_HS (out), LEG2_LS (out), LEG3_HS (out), LEG3_LS (out), LEG4_HS (out), LEG4_LS (out), ORING_EN (out), PRI_FAULT_SEC (in), PSFB_ON (in), PSFB_ON (out), PWM_ACL (out), PWM_DEBUG_SEC (in), SEC_SCI_RX0 (in), SEC_SCI_TX0 (out), TMP_SEC (in), VLV_FB1 (in), VLV_FB1 (out), VLV_FB (in), VLV_FB (out), Vout_SNS+ (in)

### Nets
SGND: C200.2 C201.2 C202.2 C203.2 C205.2 C206.2 C208.2 C209.2 C210.2 C211.1 C213.1 C214.2 C215.2 C216.2 C217.2 C218.2 C219.2 C220.2 J200.7 J200.10 J200.13 J200.16 J200.19 J200.22 J200.29 J200.35 J200.38 J200.46 J200.47 J200.65 J200.83 J200.97 J200.111 R202.1 R207.1 R208.1 R209.1 R212.2 R219.1 R222.1 R225.1 R227.1 R231.1 R232.1 R234.1 R235.1 RT200.1 SGND#2.1 SGND#3.1 SGND#4.1 U200.2(V-) U201.1(PGND) U201.4(AGND) U201.9(PAD) U202.2(GND) U203.2(GND) U204.2(GND)
3V3s: C206.1 C217.1 R213.1 R215.2 U200.5(V+) U203.5(OUT) ; port 3V3s
3V3sa: C208.1 R236.2 U204.5(OUT) ; port 3V3sa
5Vs: 5Vs.1 C211.2 C216.1 C218.1 C220.1 J200.84 J200.98 J200.112 L200.2 R230.2 R236.1 U201.6(VOS) U202.3(V+) U203.1(IN) U203.3(EN) U204.1(IN) U204.3(EN) ; port 5Vs
12Vs: 12Vs.1 C215.1 C219.1 U201.2(VIN) U201.3(EN) ; port 12Vs
54V1: R223.1 R229.2 ; port 54V1
54VLS-EN: J200.58 ; port 54VLS-EN
ACTIVE_EMI_SENSE_PSFB: J200.34 ; port ACTIVE_EMI_SENSE_PSFB
AD_IBUS: J200.24 ; port AD_IBUS
COIL_SEC_N: C207.2 C209.1 R215.1 R219.2 U200.3(IN+) ; port COIL_SEC_N
COIL_SEC_P: R217.1 ; port COIL_SEC_P
CS+: D201.2(A) D203.1(K) ; port CS+
CS-: D200.2(A) D202.1(K) ; port CS-
DAC_OUT: J200.9 ; port DAC_OUT
FAN_CTRL: J200.63 ; port FAN_CTRL
FAN_FB: J200.20 ; port FAN_FB
IHV_FB: C202.1 J200.15 R205.2 ; port IHV_FB
ILV_FB: C213.2 J200.14 R224.1 R227.2 ; port ILV_FB
ILV_ZCD: J200.18 R218.2 ; port ILV_ZCD
Iout_SNS: R226.1 ; port Iout_SNS
LEG1_FLT: R200.2 ; port LEG1_FLT
LEG1_HS: J200.49 ; port LEG1_HS
LEG1_LS: J200.51 ; port LEG1_LS
LEG2_FLT: R203.2 ; port LEG2_FLT
LEG2_HS: J200.53 ; port LEG2_HS
LEG2_LS: J200.55 ; port LEG2_LS
LEG3_HS: J200.50 ; port LEG3_HS
LEG3_LS: J200.52 ; port LEG3_LS
LEG4_HS: J200.54 ; port LEG4_HS
LEG4_LS: J200.56 ; port LEG4_LS
ORING_EN: J200.59 ; port ORING_EN
PRI_FAULT_SEC: J200.74 ; port PRI_FAULT_SEC
PSFB_ON: J200.68 R225.2 R233.2 ; port PSFB_ON
PWM_ACL: J200.61 ; port PWM_ACL
PWM_DEBUG_SEC: R211.1 ; port PWM_DEBUG_SEC
SEC_SCI_RX0: J200.76 ; port SEC_SCI_RX0
SEC_SCI_TX0: J200.78 ; port SEC_SCI_TX0
TMP_SEC: C205.1 J200.12 R213.2 RT200.2 ; port TMP_SEC
VLV_FB: C214.1 J200.23 R228.1 R231.2 ; port VLV_FB
VLV_FB1: C210.1 J200.17 R220.1 R222.2 ; port VLV_FB1
Vout_SNS+: R221.2 ; port Vout_SNS+
NetC200_1: C200.1 R200.1 R201.2 R202.2
NetC201_1: C201.1 R203.1 R204.2 R207.2
NetC203_1: C203.1 J200.57 R211.2
NetC204_1: C204.1 R214.2 R218.1 U200.1(OUT)
NetC204_2: C204.2 R214.1 R216.2 U200.4(IN-)
NetC207_1: C207.1 R216.1 R217.2
NetC212_1: C212.1 R223.2 U202.5(VIN-)
NetC212_2: C212.2 R226.2 U202.4(VIN+)
NetD200_1: D200.1(K) D201.1(K) R206.1 R210.1
NetD202_2: D202.2(A) D203.2(A) R210.2 R212.1
NetJ200_62: J200.62 R201.1
NetJ200_64: J200.64 R204.1
NetL200_1: L200.1 U201.7(SW)
NetPSON_1: PSON.1 R233.1
NetR205_1: R205.1 R206.2 R208.2 R209.2 R234.2 R235.2
NetR220_2: R220.2 R221.1
NetR224_2: R224.2 U202.1(OUT)
NetR228_2: R228.2 R229.1
NetR230_1: R230.1 R232.2 U201.5(FB)

Not connected (* = marked no-connect by the designer): J200 1* 2* 3* 4* 5* 6* 8* 11 21 25 26* 27* 28* 30* 31* 32* 33* 36* 37* 39* 40* 41* 42* 43* 44* 45* 48* 60* 66* 67 69 70* 71 72* 73* 75* 77* 79* 80* 81* 82* 85* 86* 87 88* 89* 90* 91* 92* 93* 94* 95* 96* 99* 100* 101* 102* 103* 104* 105* 106* 107* 108* 109* 110* 113* 114* 115* 116* 117* 118* 119* 120*; U201 8(PG)*; U203 4(NC); U204 4(NC)

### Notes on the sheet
- 100V/V
- (near SGND#3) 12Vs
- 5Vs
- (near C218) 0.1Amax
- (near C217) 0.1Amax
- (near C220) 0.1Amax
- (near C208) 0.1Amax

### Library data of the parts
5Vs 12Vs = 5000: as 5Vp on sheet PMP22951_Main_PSFB
C200 C201 C203 = GRM155R70J103KA01D: CAP, CERM, 0.01uF, 6.3V, +/-10%, X7R, 0402; Manufacturer: MuRata; Polarized: N; CompType: Capacitor; U/M: EA; Cap_F: 0.00000001; Tolerance_%: 10; Value1: Unknown; VDC_V: 6.3; TaMin_C: -55; TaMax_C: 125
C202 = 885012205044: CAP, CERM, 1000 pF, 25 V,+/- 10%, X7R, 0402; Manufacturer: Wurth Elektronik; Polarized: N; CompType: Capacitor; Value: 1000pF; U/M: EA; Cap_F: 0.000000001; Tolerance_%: 10; VDC_V: 25; Value2: 25V; TaMin_C: -55; TaMax_C: 125; SizeArea_mm2: 0.5; SizeAreaWB_mm2: 3; SizeX_mm: 1; SizeZ_mm: 0.6; AEC Category: Q200
C204 = GRM1555C1H2R2BA01D: CAP, CERM, 2.2 pF, 50 V,+/- 5%, C0G/NP0, 0402; Manufacturer: MuRata; Polarized: N; CompType: Capacitor; Value: 2.2pF; U/M: EA; Cap_F: 0.0000000000022; Tolerance_%: 5; VDC_V: 50; Value2: 50V; TaMin_C: -55; TaMax_C: 125; SizeArea_mm2: 0.5; SizeAreaWB_mm2: 3; SizeX_mm: 1; SizeZ_mm: 0.6; AEC Category: Q200
C205 = CMP-0006320-2: CAP, CERM, 470 pF, 50 V, +/- 10%, X7R, AEC-Q200 Grade 1, 0402; Manufacturer: TDK; TaMin_C: -55°C; ESR_ohm: 4.96489; Polarized: N; SizeAreaWB_mm2: 3; Value1: 4.96489 ohm; U/M: EA; Value: 470pF; TaMax_C: 125°C; SizeZ_mm: 0.6; SizeX_mm: 1; SizeY_mm: 0.5; Value2: 50V; CompType: Capacitor; AEC Qualified: Y; IRMS_A: 2.28414dA; AEC Category: Q200
C206 C209 = 0402YC104KAT2A: CAP, CERM, 0.1 µF, 16 V,+/- 10%, X7R, 0402; Manufacturer: AVX; Polarized: N; CompType: Capacitor; Value: 0.1uF; U/M: EA; Cap_F: 0.0000001; Tolerance_%: 10; VDC_V: 16; Value2: 16V; TaMin_C: -55; TaMax_C: 125; SizeArea_mm2: 0.5; SizeAreaWB_mm2: 3; SizeX_mm: 1; SizeZ_mm: 0.6; AEC Category: Q200; Green_Lifecycle: Active; Green_REACh: Passed
C207 = CGA2B2X7R1H222K050BA: CAP, CERM, 2200 pF, 50 V,+/- 10%, X7R, AEC-Q200 Grade 1, 0402; Manufacturer: TDK; Polarized: N; CompType: Capacitor; Value: 2200pF; U/M: EA; Cap_F: 0.0000000022; Tolerance_%: 10; ESR_ohm: 1.07794; Value1: 1.07794 ohm; VDC_V: 50; Value2: 50V; IRMS_A: 0.264071; TaMin_C: -55; TaMax_C: 125; SizeArea_mm2: 0.5; SizeAreaWB_mm2: 3; SizeX_mm: 1; SizeZ_mm: 0.6; AEC Category: Q200; AEC Qualified: Y
C208 C217 C218 C220 = GRM155R70J104KA01D: CAP, CERM, 0.1uF, 6.3V, +/-10%, X7R, 0402; Manufacturer: MuRata; Polarized: N; CompType: Capacitor; U/M: EA; Cap_F: 0.0000001; Tolerance_%: 10; Value1: Unknown; VDC_V: 6.3; TaMin_C: -55; TaMax_C: 125
C210 C214 = 06035A102KAT2A: CAP, CERM, 1000pF, 50V, +/-10%, C0G/NP0, 0603; Manufacturer: AVX; Polarized: N; CompType: Capacitor; U/M: EA; Cap_F: 0.000000001; Tolerance_%: 10; ESR_Ohm: 0.048; Value1: 0.048 ohm; VDC_V: 50; TaMin_C: -55; TaMax_C: 125
C211 = C1608X7R1E105K080AB: CAP, CERM, 1uF, 25V, +/-10%, X7R, 0603; Manufacturer: TDK; Polarized: N; CompType: Capacitor; U/M: EA; Cap_F: 0.000001; Tolerance_%: 10; Value1: Unknown; VDC_V: 25; TaMin_C: -55; TaMax_C: 125
C212 = GRM1555C1E4R7CA01D: CAP, CERM, 4.7 pF, 25 V,+/- 5%, C0G/NP0, 0402; Manufacturer: MuRata; Polarized: N; CompType: Capacitor; Value: 4.7pF; U/M: EA; Cap_F: 0.0000000000047; Tolerance_%: 5; VDC_V: 25; Value2: 25V; TaMin_C: -55; TaMax_C: 125; SizeArea_mm2: 0.5; SizeAreaWB_mm2: 3; SizeX_mm: 1; SizeZ_mm: 0.6; AEC Category: Q200; Green_Lifecycle: Active; Green_REACh: Passed
C213 = 0402YC101KAT2A: CAP, CERM, 100 pF, 16 V,+/- 10%, X7R, 0402; Manufacturer: AVX; Polarized: N; CompType: Capacitor; Value: 100pF; U/M: EA; Cap_F: 0.0000000001; Tolerance_%: 10; VDC_V: 16; TaMin_C: -55; TaMax_C: 125; SizeArea_mm2: 0.5; SizeAreaWB_mm2: 3; SizeX_mm: 1; SizeZ_mm: 0.6; AEC Category: Q200
C215 = CMP-0007728-2: CAP, CERM, 1 uF, 25 V, +/- 10%, X7R, 0805; Manufacturer: Kemet; TaMin_C: -55°C; Polarized: N; SizeAreaWB_mm2: 6.75; Value1: Unknown; U/M: EA; Value: 1uF; TaMax_C: 125°C; SizeZ_mm: 1.45; SizeX_mm: 2; SizeY_mm: 1.25; Cap_Case: 0805; SizeArea_mm2: 2.5; AEC Category: Q200
C216 = CMP-0007989-2: CAP, CERM, 22 uF, 6.3 V, +/- 10%, X5R, 0805; Manufacturer: Samsung Electro-Mechanics; TaMin_C: -55°C; Polarized: N; SizeAreaWB_mm2: 6.75; Value1: Unknown; U/M: EA; Value: 22uF; TaMax_C: 85°C; SizeZ_mm: 1.45; SizeX_mm: 2; SizeY_mm: 1.25; Cap_Case: 0805; SizeArea_mm2: 2.5; Cap_F: 22µF; AEC Category: Q200
C219 = GCM31CR71C106KA64L: as C125 on sheet PMP22951_Main_PSFB
D200-D203 = BAS316,115: Diode, Ultrafast, 100 V, 0.25 A, SOD-323; Manufacturer: Nexperia; U/M: EA; Vf_V: 1.4; Value: 100V; Value1: 0.25A; Value2: 1.4V; Io_A: 0.25; Vr_V: 100; TJmax_C: 150; SizeAreaWB_mm2: 8.695; SizeArea_mm2: 3.645; SizeX_mm: 2.7; SizeY_mm: 1.35; SizeZ_mm: 1; AEC Category: Q101; Green_Lifecycle: Not Set; Green_REACh: Incomplete
J200 = controlCARD-120HSEC: C2000 controlCARD-120HSEC connector, SMT; Manufacturer: Samtec; SymbolCreator: a0412235; Note: The pin numbering does not match Samtec datasheet
L200 = CMP-0087867-1: as L103 on sheet PMP22951_Main_PSFB
PSON = 5003: Test Point, Miniature, Orange, TH; Manufacturer: Keystone; CompType: Test Point Loop; ContactFinish: Silver; Green_Lifecycle: Active; Green_REACh: Passed
R200 R203 = CRCW04024K99FKED: RES, 4.99 k, 1%, 0.063 W, 0402; Manufacturer: Vishay-Dale; CompType: Resistor; Value: 4.99k; Res_ohm: 4990; Value_Code: 4k99; Tolerance_%: 1; Power_W: 0.063; Value2: 0.063W; VDC_V: 50; TempCo: 100 ppm/C; SizeArea_mm2: 0.5; SizeZ_mm: 0.6; EIA_Code: E96; U/M: EA; AEC Category: Q200
R201 R204 R221 R229 = CRCW0603100RFKEA: RES, 100, 1%, 0.1 W, 0603; Manufacturer: Vishay-Dale; CompType: Resistor; Value: 100; Value_Code: 100R; Tolerance_%: 1; Power_W: 0.1; Value2: 0.1W; VDC_V: 75; TempCo: 100 ppm/C; SizeArea_mm2: 1.28; SizeX_mm: 1.6; SizeY_mm: 0.8; EIA_Code: E96; U/M: EA; AEC Category: Q200; Green_Lifecycle: Active; Green_REACh: Passed
R202 R207 = CRCW04029K31FKED: RES, 9.31 k, 1%, 0.063 W, 0402; Manufacturer: Vishay-Dale; CompType: Resistor; Value: 9.31k; Res_ohm: 9310; Value_Code: 9k31; Tolerance_%: 1; Power_W: 0.063; Value2: 0.063W; VDC_V: 50; TempCo: 100 ppm/C; SizeArea_mm2: 0.5; SizeZ_mm: 0.6; EIA_Code: E96; U/M: EA; AEC Category: Q200
R205 R206 R212 = CRCW04020000Z0ED: RES, 0, 5%, 0.063 W, 0402; Manufacturer: Vishay-Dale; CompType: Resistor; Value: 0; Value_Code: 0000; Tolerance_%: 5; Power_W: 0.063; Value2: 0.063W; VDC_V: 50; TempCo: 200 ppm/C; SizeArea_mm2: 0.5; SizeX_mm: 1; SizeZ_mm: 0.6; EIA_Code: E24; U/M: EA; AEC Category: Q200; Green_Lifecycle: Active; Green_REACh: Passed
R208 R209 R234 R235 = CRCW120614R7FKEA: RES, 14.7, 1%, 0.25 W, 1206; Manufacturer: Vishay-Dale; CompType: Resistor; Value: 14.7; Value_Code: 14R7; Tolerance_%: 1; Power_W: 0.25; Value2: 0.25W; VDC_V: 200; TempCo: 100 ppm/C; SizeArea_mm2: 5.12; SizeX_mm: 3.2; SizeY_mm: 1.6; SizeZ_mm: 1.35; EIA_Code: E96; U/M: EA; AEC Category: Q200
R210 = RC0603FR-079k76L: RES, 9.76 k, 1%, 0.1 W, 0603; Manufacturer: Yageo America; CompType: Resistor; Value: 9.76k; Res_ohm: 9760; Value_Code: 9k76; Tolerance_%: 1; Power_W: 0.1; Value2: 0.1W; VDC_V: 150; TempCo: 200 ppm/C; SizeArea_mm2: 1.28; SizeX_mm: 1.6; SizeY_mm: 0.8; EIA_Code: E96; U/M: EA; AEC Category: Q200
R211 = CRCW04021K40FKED: RES, 1.40k ohm, 1%, 0.063W, 0402; Manufacturer: Vishay-Dale; CompType: Resistor; Res_ohm: 1400; Value_Code: 1k40; Tolerance_%: 1; Power_W: 0.063; VDC_V: 50; TempCo: 100 ppm/C; EIA_Code: E96; U/M: EA
R213 = CRCW040210K0FKED: RES, 10.0 k, 1%, 0.063 W, 0402; Manufacturer: Vishay-Dale; CompType: Resistor; Value: 10.0k; Res_ohm: 10000; Value_Code: 10k0; Tolerance_%: 1; Power_W: 0.063; Value2: 0.063W; VDC_V: 50; TempCo: 100 ppm/C; SizeArea_mm2: 0.5; SizeZ_mm: 0.6; EIA_Code: E96; U/M: EA; AEC Category: Q200
R214 = CRCW04023K65FKED: RES, 3.65 k, 1%, 0.063 W, 0402; Manufacturer: Vishay-Dale; CompType: Resistor; Value: 3.65k; Res_ohm: 3650; Value_Code: 3k65; Tolerance_%: 1; Power_W: 0.063; Value2: 0.063W; VDC_V: 50; TempCo: 100 ppm/C; SizeArea_mm2: 0.5; SizeZ_mm: 0.6; EIA_Code: E96; U/M: EA; AEC Category: Q200
R215 R219 = CRCW040210K0FKED: RES, 10.0 k, 1%, 0.063 W, 0402; Manufacturer: Vishay-Dale; CompType: Resistor; Value: 10.0k; Res_ohm: 10000; Value_Code: 10k0; Tolerance_%: 1; Power_W: 0.063; Value2: 0.063W; VDC_V: 50; TempCo: 100 ppm/C; SizeArea_mm2: 0.5; SizeZ_mm: 0.6; EIA_Code: E96; U/M: EA; AEC Category: Q200; Green_Lifecycle: Active; Green_REACh: Passed
R216 R217 R233 = CRCW04021K00FKED: RES, 1.00 k, 1%, 0.063 W, 0402; Manufacturer: Vishay-Dale; CompType: Resistor; Value: 1.00k; Res_ohm: 1000; Value_Code: 1k00; Tolerance_%: 1; Power_W: 0.063; Value2: 0.063W; VDC_V: 50; TempCo: 100 ppm/C; SizeArea_mm2: 0.5; SizeZ_mm: 0.6; EIA_Code: E96; U/M: EA; AEC Category: Q200; Green_Lifecycle: Active; Green_REACh: Passed
R218 = CRCW040256R2FKED: RES SMD 56.2 OHM 1% 1/16W 0402; Manufacturer: Yageo; CompType: Resistor; Value: 56.2; Value_Code: 56R2; Tolerance_%: 1; Power_W: 0.063; Value2: 0.063W; VDC_V: 50; TempCo: 100 ppm/C; SizeArea_mm2: 0.5; SizeZ_mm: 0.6; EIA_Code: E96; U/M: EA; AEC Category: Q200
R220 R228 = CRCW120637K4FKEA: RES, 37.4 k, 1%, 0.25 W, 1206; Manufacturer: Vishay-Dale; CompType: Resistor; Value: 37.4k; Res_ohm: 37400; Value_Code: 37k4; Tolerance_%: 1; Power_W: 0.25; Value2: 0.25W; VDC_V: 200; TempCo: 100 ppm/C; SizeArea_mm2: 5.12; SizeX_mm: 3.2; SizeY_mm: 1.6; SizeZ_mm: 1.35; EIA_Code: E96; U/M: EA; AEC Category: Q200
R222 R231 = RC0603FR-071K82L: RES, 1.82 k, 1%, 0.1 W, 0603; Manufacturer: Yageo America; CompType: Resistor; Value: 1.82k; Res_ohm: 1820; Value_Code: 1k82; Tolerance_%: 1; Power_W: 0.1; Value2: 0.1W; VDC_V: 150; TempCo: 200 ppm/C; EIA_Code: E96; U/M: EA; SizeArea_mm2: 1.28; SizeX_mm: 1.6; SizeY_mm: 0.8; AEC Category: Q200; Green_Lifecycle: Active; Green_REACh: Passed
R223 R226 = RC0603FR-074R75L: RES, 4.75, 1%, 0.1 W, 0603; Manufacturer: Yageo America; CompType: Resistor; Value: 4.75; Value_Code: 4R75; Tolerance_%: 1; Power_W: 0.1; Value2: 0.1W; VDC_V: 150; TempCo: 200 ppm/C; SizeArea_mm2: 1.28; SizeX_mm: 1.6; SizeY_mm: 0.8; EIA_Code: E96; U/M: EA; AEC Category: Q200
R224 = RC0603FR-0724KL: RES, 24.0 k, 1%, 0.1 W, 0603; Manufacturer: Yageo America; CompType: Resistor; Value: 24.0k; Res_ohm: 24000; Value_Code: 24k0; Tolerance_%: 1; Power_W: 0.1; Value2: 0.1W; VDC_V: 150; TempCo: 200 ppm/C; SizeArea_mm2: 1.28; SizeX_mm: 1.6; SizeY_mm: 0.8; U/M: EA; AEC Category: Q200; Green_Lifecycle: Active; Green_REACh: Passed
R225 = CRCW120610K0FKEA: RES, 10.0 k, 1%, 0.25 W, 1206; Manufacturer: Vishay-Dale; CompType: Resistor; Value: 10.0k; Res_ohm: 10000; Value_Code: 10k0; Tolerance_%: 1; Power_W: 0.25; Value2: 0.25W; VDC_V: 200; TempCo: 100 ppm/C; SizeArea_mm2: 5.12; SizeX_mm: 3.2; SizeY_mm: 1.6; SizeZ_mm: 1.35; EIA_Code: E96; U/M: EA; AEC Category: Q200; Green_Lifecycle: Active; Green_REACh: Passed
R227 = CRCW0603100KFKEA: RES, 100 k, 1%, 0.1 W, 0603; Manufacturer: Vishay-Dale; CompType: Resistor; Value: 100k; Res_ohm: 100000; Tolerance_%: 1; Power_W: 0.1; Value2: 0.1W; VDC_V: 75; TempCo: 100 ppm/C; SizeArea_mm2: 1.28; SizeX_mm: 1.6; SizeY_mm: 0.8; EIA_Code: E96; U/M: EA; AEC Category: Q200; Green_Lifecycle: Active; Green_REACh: Passed
R230 = CMP-0026504-2: RES, 681 k, 1%, 0.063 W, AEC-Q200 Grade 0, 0402; Manufacturer: Vishay-Dale; Power_W: 63mW; TempCo: 100 ppm/C; Value: 681k; EIA_Code: E96; SizeX_mm: 1; SizeY_mm: 0.5; SizeZ_mm: 0.6; Value2: 0.063W; AEC Qualified: Y; VDC_V: 50V; AEC Category: Q200; AEC Grade: 0
R232 = CMP-0025997-3: RES, 130 k, 1%, 0.063 W, AEC-Q200 Grade 0, 0402; Manufacturer: Vishay-Dale; Power_W: 63mW; TempCo: 100 ppm/C; Value: 130k; EIA_Code: E96; SizeX_mm: 1; SizeY_mm: 0.5; SizeZ_mm: 0.6; Value2: 0.063W; AEC Qualified: Y; VDC_V: 50V; AEC Category: Q200; AEC Grade: 0
R236 = CRCW12060000Z0EA: RES, 0, 5%, 0.25 W, 1206; Manufacturer: Vishay-Dale; CompType: Resistor; Value: 0; Value_Code: 0000; Tolerance_%: 5; Power_W: 0.25; Value2: 0.25W; VDC_V: 200; TempCo: 200 ppm/C; SizeArea_mm2: 5.12; SizeX_mm: 3.2; SizeY_mm: 1.6; SizeZ_mm: 1.35; EIA_Code: E24; U/M: EA; AEC Category: Q200; Green_Lifecycle: Active; Green_REACh: Passed
RT200 = CMP-0084566-1: Thermistor, DEC0002A (X1SON-2); Alternate Manufacturer: Texas Instruments; Alternate PartNumber: TMP6131DECT; CompType: IC; AEC Category: Q200; SizeX_mm: 1; AEC Qualified: N; SizeZ_mm: 0.5; SizeArea_mm2: 0.6; SizeAreaWB_mm2: 3.2
SGND#2-SGND#4 = 5001: as PGND#2 on sheet PMP22951_Main_PSFB
U200 = CMP-0068461-2: Low Voltage, 45MHz, Rail-to-Rail Output Operational Amplifiers with Shutdown Option, DBV0005A (SOT-23-5); Manufacturer: Texas Instruments; CompType: IC; AEC Category: Q200; AEC Qualified: N; Rating: Catalog; SizeAreaWB_mm2: 14.82; SizeArea_mm2: 8.12; SizeX_mm: 2.8; SizeY_mm: 2.9; SizeZ_mm: 1.45
U201 = CMP-0067100-2: as U101 on sheet PMP22951_Main_PSFB
U202 = CMP-0750220-2: INA293 High-Voltage, High Bandwidth, Unidirectional, 110-V Common-Mode, Current-Sense Amplifier, DBV0005A (SOT-23-5); Alternate PartNumber: INA293B3IDBVT; Manufacturer: Texas Instruments; AEC Category: Q200; AEC Qualified: N; SizeAreaWB_mm2: 14.82; SizeX_mm: 2.8; SizeZ_mm: 1.45; CompType: IC; SizeArea_mm2: 8.12; SizeY_mm: 2.9
U203 U204 = TLV71333PQDBVRQ1: Capacitor-Free, 150-mA, Low-Dropout Regulator with Foldback Current Limit for Portable Devices, DBV0005A; Manufacturer: Texas Instruments; SymbolCreator: Altium; SizeArea_mm2: 8.12; SizeAreaWB_mm2: 14.82; SizeX_mm: 2.8; SizeY_mm: 2.9; SizeZ_mm: 1.45; CompType: IC; U/M: EA

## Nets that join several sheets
SGND: PMP22951_Main_PSFB (20 pins), PMP22951_Main_Controller (57 pins)
5Vs: PMP22951_Main_PSFB (J102.2 J102.4), PMP22951_Main_Controller (17 pins)
12Vs: PMP22951_Main_PSFB (J102.5 J102.11), PMP22951_Main_Controller (5 pins)
54V1: PMP22951_Main_PSFB (31 pins), PMP22951_Main_Controller (R223.1 R229.2)
COIL_SEC_N: PMP22951_Main_PSFB (L102.2), PMP22951_Main_Controller (5 pins)
COIL_SEC_P: PMP22951_Main_PSFB (L102.1), PMP22951_Main_Controller (R217.1)
CS+: PMP22951_Main_PSFB (CT100.1 CT101.1), PMP22951_Main_Controller (D201.2 D203.1)
CS-: PMP22951_Main_PSFB (CT100.3 CT101.3), PMP22951_Main_Controller (D200.2 D202.1)
Iout_SNS: PMP22951_Main_PSFB (11 pins), PMP22951_Main_Controller (R226.1)
LEG3_HS: PMP22951_Main_PSFB (J102.1), PMP22951_Main_Controller (J200.50)
LEG3_LS: PMP22951_Main_PSFB (J102.3), PMP22951_Main_Controller (J200.52)
LEG4_HS: PMP22951_Main_PSFB (J102.7), PMP22951_Main_Controller (J200.54)
LEG4_LS: PMP22951_Main_PSFB (J102.9), PMP22951_Main_Controller (J200.56)
ORING_EN: PMP22951_Main_PSFB (U100.6), PMP22951_Main_Controller (J200.59)
PWM_ACL: PMP22951_Main_PSFB (J102.6), PMP22951_Main_Controller (J200.61)
Vout_SNS+: PMP22951_Main_PSFB (R102.2), PMP22951_Main_Controller (R221.2)

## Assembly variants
001: not fitted C107 C123 C124 C125 L100 L102 R213 R234 R235 R236 RT200 SGND T100 TP100 TP109 TP110 Vout+ Vout-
